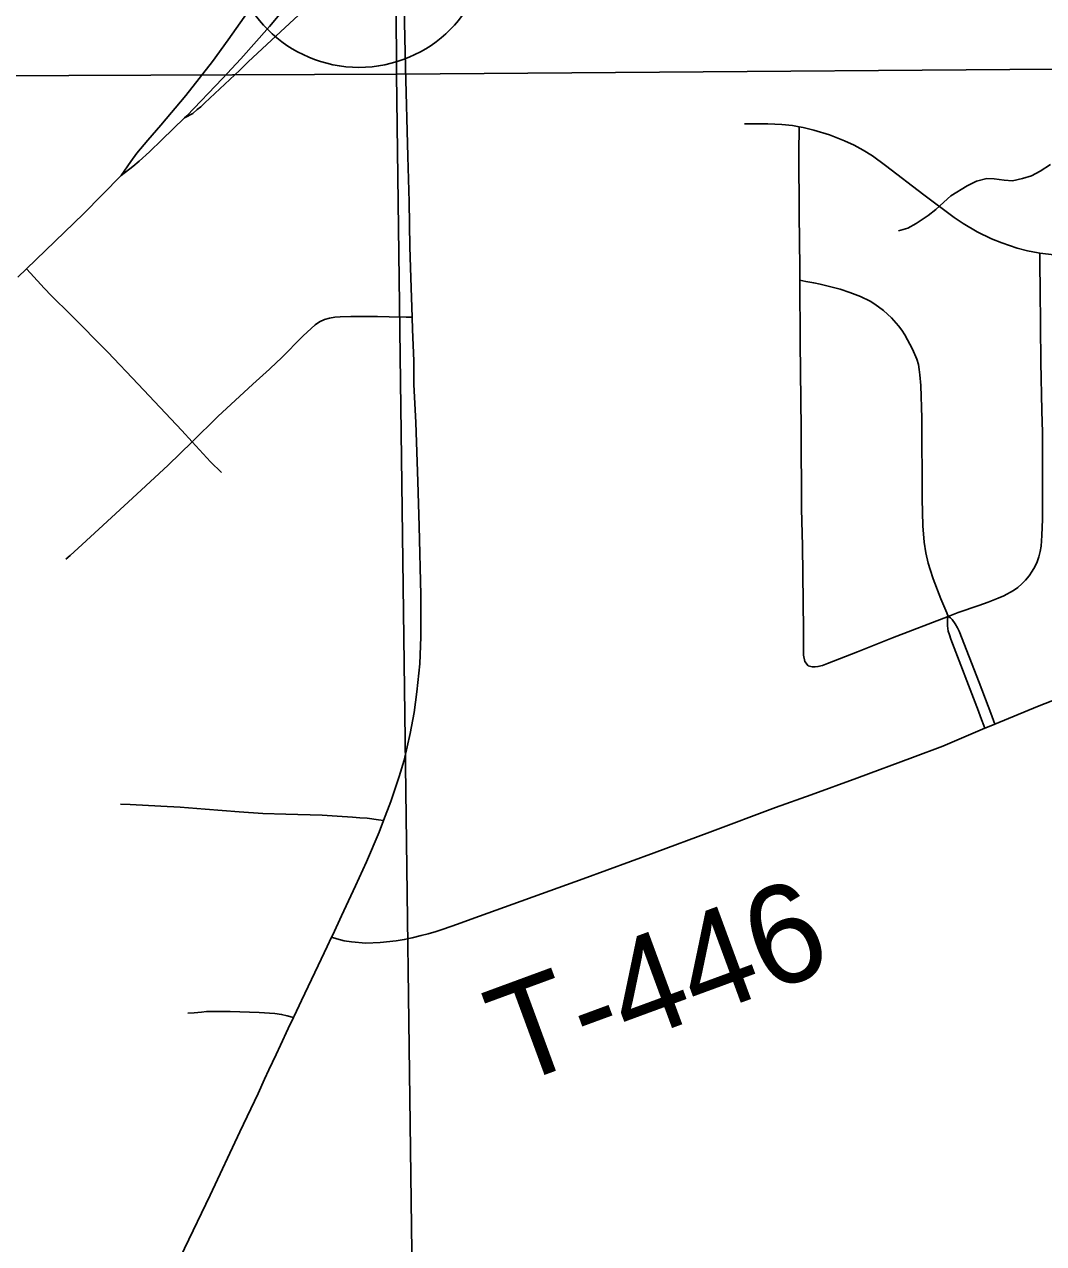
# Model space of a CAD drawing. Extents: x 0 to 34, y 0 to 22.
# Drawn here: x 6.57 to 7.158, y 18.2 to 18.904 of the extents above; entities that cross this region are included whole.
import ezdxf

# ---------------------------------------------------------------- set-up
doc = ezdxf.new("R2010")
doc.units = 0
for name, color, linetype in [('GM_X_Interchange_Ramps', 7, 'Continuous'), ('GM_X_Minor_River', 7, 'Continuous'), ('GM_X_Section', 7, 'Continuous'), ('GM_X_State_Route', 7, 'Continuous'), ('GM_X_Township_Road', 7, 'Continuous'), ('GM_X_Township_Road_Text', 7, 'Continuous'), ('GM_X_Unincorporated', 7, 'Continuous')]:
    doc.layers.add(name, color=color, linetype=linetype)

msp = doc.modelspace()

# ---------------------------------------------------------------- linework, layer by layer
at = {"layer": 'GM_X_Interchange_Ramps'}
msp.add_lwpolyline([(6.66245, 18.8501), (6.66708, 18.8527), (6.66974, 18.85485), (6.6717, 18.85645), (6.67409, 18.8587), (6.69436, 18.87773), (6.69902, 18.88245), (6.71262, 18.89486), (6.74618, 18.92636), (6.76641, 18.9452), (6.78241, 18.95926), (6.78468, 18.96139), (6.78614, 18.96329), (6.78846, 18.96683)], dxfattribs=at)
at = {"layer": 'GM_X_Minor_River'}
msp.add_lwpolyline([(7.16209, 18.82328), (7.15605, 18.8194), (7.15114, 18.81668), (7.14584, 18.81508), (7.14015, 18.81387), (7.1352, 18.81418), (7.12949, 18.81487), (7.1253, 18.81519), (7.11923, 18.81359), (7.11394, 18.81086), (7.10451, 18.80504), (7.10038, 18.80156), (7.09587, 18.79732), (7.09135, 18.79384), (7.08456, 18.7892), (7.07965, 18.78647), (7.07435, 18.78488)], dxfattribs=at)
at = {"layer": 'GM_X_Section'}
for points in [[(5.65424, 19.88127), (6.77985, 19.89133), (6.78469, 18.87524), (5.64995, 18.87081), (5.64978, 18.89848)], [(6.77985, 19.89133), (7.78202, 19.88507), (7.79585, 18.88307), (6.78469, 18.87524)], [(7.79585, 18.88307), (7.79423, 17.86732), (6.79787, 17.8558), (6.78469, 18.87524)], [(5.64995, 18.87081), (6.78469, 18.87524), (6.79787, 17.8558), (5.64653, 17.84104), (5.64681, 17.91722)]]:
    msp.add_lwpolyline(points, close=True, dxfattribs=at)
at = {"layer": 'GM_X_State_Route'}
for points in [[(6.6259, 18.81692), (6.63147, 18.82492), (6.63492, 18.82969), (6.64117, 18.83725), (6.64874, 18.84596), (6.66321, 18.86293), (6.67854, 18.88256), (6.68757, 18.89524), (6.70378, 18.91803), (6.72272, 18.94512), (6.7305, 18.95626), (6.75563, 18.99181), (6.77502, 19.02001), (6.78865, 19.04084), (6.7954, 19.05185), (6.80166, 19.06208), (6.80466, 19.06724)], [(6.6259, 18.81692), (6.63245, 18.82213), (6.63624, 18.82508), (6.64225, 18.83058), (6.64931, 18.83744), (6.66245, 18.8501), (6.66362, 18.85123), (6.68429, 18.8728), (6.69492, 18.88414), (6.71133, 18.90284), (6.72926, 18.92434), (6.74477, 18.94379), (6.74535, 18.94469), (6.75586, 18.9588), (6.77008, 18.97923), (6.78204, 18.99742), (6.78731, 19.00588)], [(6.71776, 18.31494), (6.72223, 18.32457), (6.72529, 18.33104), (6.72563, 18.33175), (6.72994, 18.34085), (6.73374, 18.3489), (6.73947, 18.36101), (6.74467, 18.37189), (6.74724, 18.37727), (6.74788, 18.37862), (6.75297, 18.3896), (6.76105, 18.40703), (6.7673, 18.42085), (6.77471, 18.43795), (6.77724, 18.44456), (6.78145, 18.45554), (6.78623, 18.47002), (6.78902, 18.47955), (6.79264, 18.49485), (6.79494, 18.50701), (6.79643, 18.51886), (6.79807, 18.53497), (6.79874, 18.55059), (6.79874, 18.57493), (6.79776, 18.61456), (6.79695, 18.64021), (6.7958, 18.67442), (6.79476, 18.69625), (6.79466, 18.70995), (6.794, 18.72803), (6.79377, 18.73514), (6.79304, 18.7578), (6.79245, 18.77572), (6.79205, 18.80171), (6.79123, 18.82786), (6.78996, 18.87934), (6.78904, 18.91355)], [(6.56613, 18.75814), (6.5712, 18.76302), (6.60416, 18.79476), (6.6259, 18.81692)], [(6.38213, 17.59896), (6.43069, 17.70195), (6.44566, 17.73352), (6.4637, 17.77304), (6.48226, 17.8124), (6.50346, 17.85735), (6.50517, 17.86107), (6.51896, 17.89124), (6.53378, 17.92201), (6.56412, 17.98707), (6.58321, 18.02818), (6.5992, 18.06259), (6.64276, 18.15535), (6.66241, 18.1976), (6.67722, 18.22837), (6.69424, 18.265), (6.70481, 18.28721), (6.70858, 18.29538), (6.71096, 18.30085), (6.71531, 18.30969), (6.71776, 18.31494)]]:
    msp.add_lwpolyline(points, dxfattribs=at)
at = {"layer": 'GM_X_Township_Road'}
for points in [[(6.98555, 18.8466), (6.99888, 18.8466), (7.00705, 18.84621), (7.01325, 18.84562), (7.01705, 18.84494)], [(7.01748, 18.7564), (7.01746, 18.76363), (7.01692, 18.79455), (7.01672, 18.82965), (7.01705, 18.84494)], [(7.01705, 18.84494), (7.01938, 18.84453), (7.02545, 18.84306), (7.03443, 18.84023), (7.04307, 18.83678), (7.04867, 18.83432), (7.054, 18.83147), (7.05926, 18.8282), (7.06678, 18.82269), (7.08891, 18.80566), (7.10639, 18.79264), (7.11154, 18.78913), (7.11962, 18.78444), (7.12807, 18.78033), (7.13386, 18.77794), (7.14275, 18.77497), (7.14882, 18.77334), (7.15494, 18.77219), (7.15589, 18.77208)], [(7.10306, 18.56246), (7.10877, 18.56466), (7.12058, 18.5687), (7.12607, 18.57062), (7.12892, 18.57173), (7.13184, 18.57289), (7.1351, 18.57437), (7.14059, 18.57735), (7.14315, 18.57913), (7.14551, 18.58117), (7.14768, 18.58342), (7.14963, 18.58585), (7.15139, 18.58844), (7.15296, 18.59113), (7.15432, 18.59394), (7.15536, 18.59688), (7.15611, 18.59991), (7.15663, 18.60299), (7.15711, 18.60921), (7.15731, 18.61858), (7.15731, 18.63642), (7.15731, 18.66852), (7.15698, 18.68101), (7.15644, 18.70911), (7.15607, 18.75153), (7.15595, 18.76518), (7.15589, 18.77208)], [(7.15589, 18.77208), (7.16421, 18.77104), (7.17354, 18.77068), (7.20157, 18.77072), (7.22339, 18.77136)], [(6.68374, 18.64543), (6.67736, 18.65164), (6.67095, 18.65863), (6.66674, 18.66324), (6.66075, 18.6698), (6.63555, 18.69641), (6.61813, 18.71498), (6.5966, 18.73674), (6.58557, 18.74739), (6.58131, 18.75188), (6.57342, 18.76057), (6.5712, 18.76302)], [(7.09263, 18.58953), (7.0915, 18.5931), (7.09011, 18.59916), (7.08921, 18.60532), (7.08842, 18.61465), (7.08796, 18.63022), (7.08772, 18.67688), (7.08718, 18.69558), (7.08672, 18.70181), (7.08631, 18.7049), (7.08578, 18.70773), (7.08482, 18.71094), (7.08232, 18.71665), (7.07791, 18.7249), (7.07622, 18.72752), (7.07438, 18.73003), (7.07023, 18.73469), (7.06563, 18.7389), (7.06065, 18.74265), (7.05801, 18.74431), (7.05244, 18.74712), (7.04632, 18.74934), (7.04068, 18.75122), (7.02908, 18.75417), (7.0254, 18.75488), (7.02084, 18.75576), (7.01748, 18.7564)], [(7.02227, 18.53384), (7.02023, 18.53647), (7.01952, 18.53998), (7.01952, 18.55443), (7.01884, 18.60309), (7.01844, 18.62453), (7.01813, 18.6709), (7.01759, 18.72033), (7.01748, 18.7564)], [(6.59394, 18.59546), (6.59635, 18.59753), (6.60326, 18.6039), (6.61286, 18.61273), (6.63485, 18.63304), (6.653, 18.64978), (6.66674, 18.66324), (6.68159, 18.67775), (6.70184, 18.69642), (6.71133, 18.70517), (6.71564, 18.70915), (6.71787, 18.71127), (6.73091, 18.72442), (6.73776, 18.73067), (6.74027, 18.73245), (6.74306, 18.73375), (6.74604, 18.73459), (6.74908, 18.7351), (6.75216, 18.73536), (6.75833, 18.73542), (6.77379, 18.73551), (6.78045, 18.73539), (6.79016, 18.7352), (6.79377, 18.73514)], [(7.10306, 18.56246), (7.1022, 18.56449), (7.0988, 18.57253), (7.09433, 18.58419), (7.09263, 18.58953)], [(7.02227, 18.53384), (7.02458, 18.53336), (7.02623, 18.5334), (7.02778, 18.53343), (7.03042, 18.53411), (7.03342, 18.53527), (7.05064, 18.54191), (7.0709, 18.55009), (7.10306, 18.56246)], [(7.12418, 18.49785), (7.12167, 18.50441), (7.12042, 18.50768), (7.10447, 18.54935), (7.10371, 18.55172), (7.10301, 18.55389), (7.10263, 18.55693), (7.10254, 18.55967), (7.10268, 18.56114), (7.10306, 18.56246)], [(7.12999, 18.50028), (7.12765, 18.5065), (7.12094, 18.52437), (7.10937, 18.55399), (7.10831, 18.55588), (7.10694, 18.55816), (7.10524, 18.56057), (7.10424, 18.56161), (7.10306, 18.56246)], [(7.12418, 18.49785), (7.12862, 18.49972), (7.12999, 18.50028), (7.15452, 18.51045), (7.17479, 18.51841), (7.18361, 18.52137), (7.19255, 18.52395), (7.2016, 18.52606), (7.21075, 18.52769), (7.22305, 18.52939), (7.24163, 18.53124), (7.26336, 18.53318), (7.29438, 18.53606), (7.30212, 18.53678)], [(6.74724, 18.37727), (6.7503, 18.37641), (6.75441, 18.37526), (6.75869, 18.3746), (6.76691, 18.37394), (6.7753, 18.37427), (6.7845, 18.37526), (6.78911, 18.37591), (6.79366, 18.37697), (6.79898, 18.37821), (6.80288, 18.37933), (6.80759, 18.38067), (6.81164, 18.38199), (6.81986, 18.38478), (6.82785, 18.3877), (6.89231, 18.41109), (6.93335, 18.42591), (6.96544, 18.43801), (7.0034, 18.45211), (7.02391, 18.45949), (7.05025, 18.46915), (7.08239, 18.48102), (7.09989, 18.48764), (7.12418, 18.49785)], [(6.62548, 18.45403), (6.63108, 18.45382), (6.64862, 18.45284), (6.65984, 18.45229), (6.67427, 18.45114), (6.69393, 18.44964), (6.70763, 18.44875), (6.72073, 18.4483), (6.74188, 18.4477), (6.75037, 18.44725), (6.75931, 18.44665), (6.76348, 18.4462), (6.76778, 18.44597), (6.7742, 18.44501), (6.77724, 18.44456)], [(6.6643, 18.33348), (6.66786, 18.33374), (6.67219, 18.33407), (6.67514, 18.33437), (6.67991, 18.33452), (6.68403, 18.3345), (6.6888, 18.33448), (6.70542, 18.33385), (6.71451, 18.3333), (6.71839, 18.33277), (6.7215, 18.33199), (6.72529, 18.33104)]]:
    msp.add_lwpolyline(points, dxfattribs=at)
at = {"layer": 'GM_X_Unincorporated'}
msp.add_circle((6.76303, 18.95366), 0.0744, dxfattribs=at)

# ---------------------------------------------------------------- texts
at = {"layer": 'GM_X_Township_Road_Text'}
msp.add_text('T-446', height=0.056818, rotation=20.19719, dxfattribs=at).set_placement((6.85159, 18.29102))

doc.saveas('drawing.dxf')
